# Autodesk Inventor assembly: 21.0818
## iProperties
Created: 2009-01
Part Number: 21.0818
Document SubType Name: Assembly
Designer: Administrator
Description: POWER-LOCK SF
Vendor: S
Mass: 30.2235 g
Surface Area: 36.813 cm^2
Volume: 3.84743 cm^3
Density: 7.85551 g/cm^3
Author: Administrator
